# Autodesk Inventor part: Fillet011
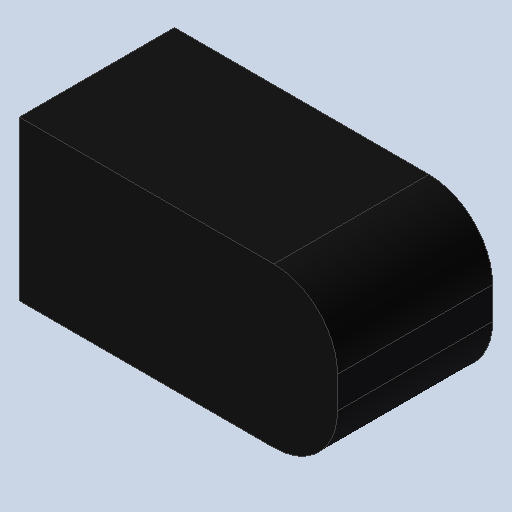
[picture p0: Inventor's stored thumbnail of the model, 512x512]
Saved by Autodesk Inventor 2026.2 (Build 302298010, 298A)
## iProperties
Created: 2026-10
Part Number: Fillet011
Material: Générique
Document SubType Name: Modeling
Designer: mel
Density: 1 g/cm^3
Appearance: Par défaut
Author: mel
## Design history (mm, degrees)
feature "Base1"
node "Solide1"
